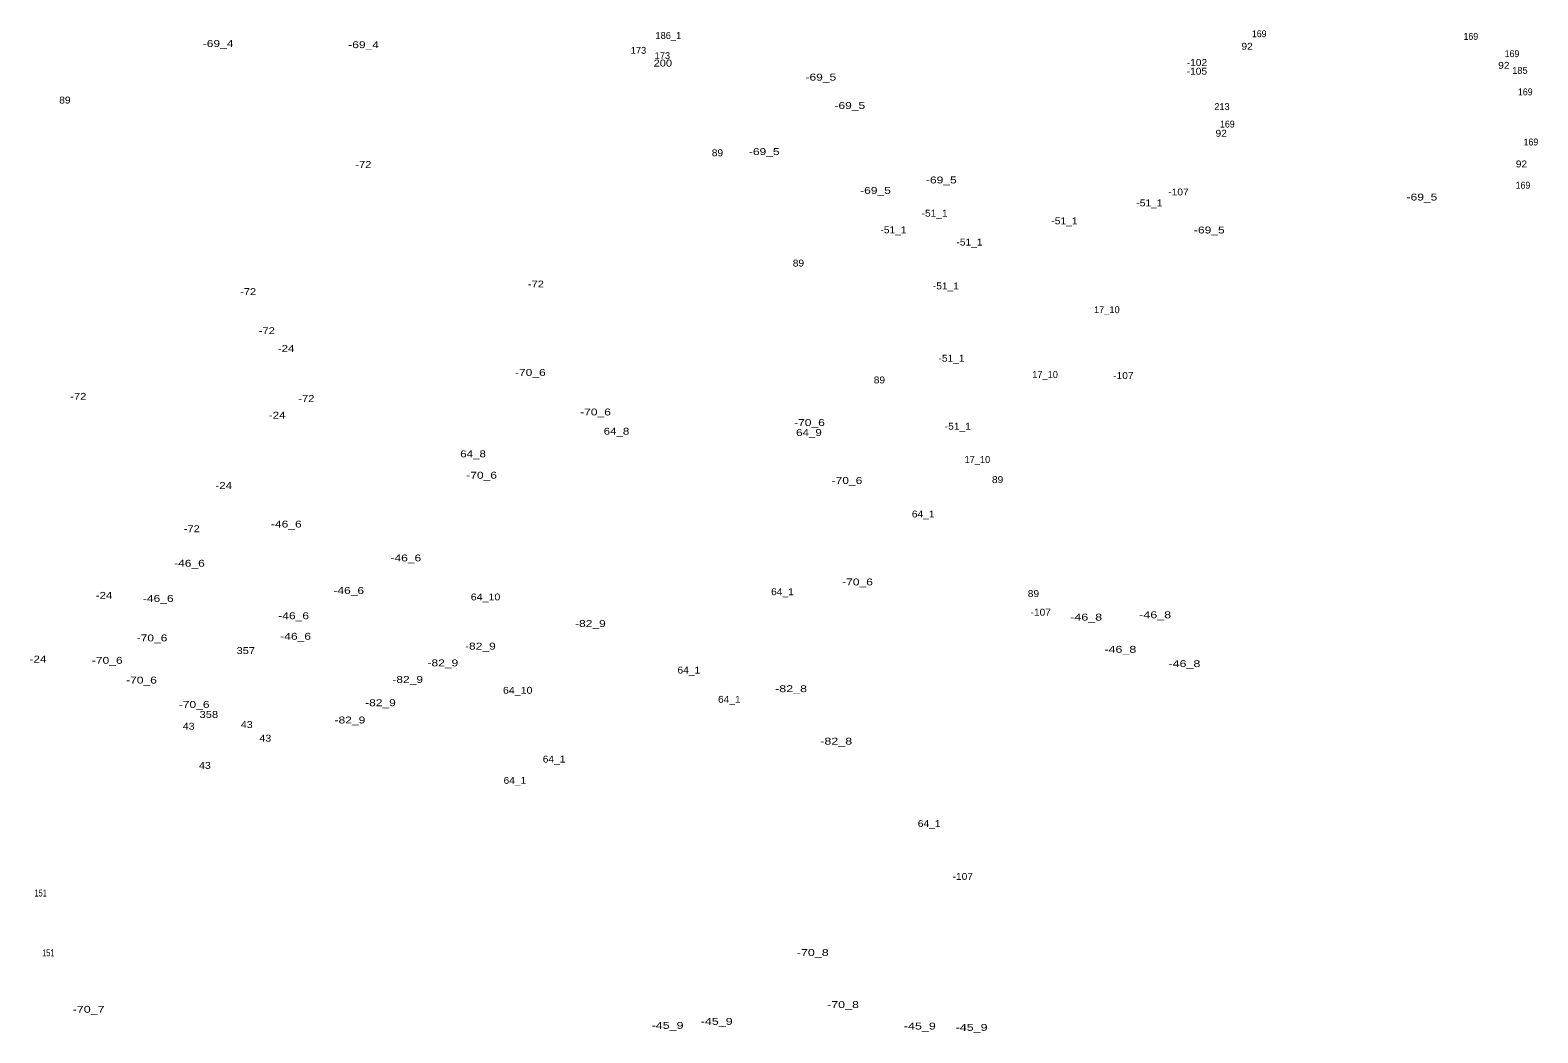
# Model space of a CAD drawing. Extents: x -662996 to -659766, y -998554 to -993949.
# Drawn here: x -660755 to -659883, y -997415 to -996835 of the extents above; entities that cross this region are included whole.
import ezdxf
from ezdxf.enums import TextEntityAlignment as Align

# ---------------------------------------------------------------- set-up
doc = ezdxf.new("R2010")
doc.units = 0
doc.header["$LTSCALE"] = 1.6
doc.layers.add('24', color=7, linetype='Continuous')

msp = doc.modelspace()

# ---------------------------------------------------------------- texts
at = {"layer": '24'}
for s, width, p in [('-69_4', 1.3, (-660646.681, -996844.98)), ('169', 0.95, (-660044.42, -996839.3)), ('169', 0.95, (-659922, -996840.84)), ('-69_4', 1.3, (-660562.52, -996845.64)), ('92', 1.1, (-660051.45, -996846.57)), ('169', 0.95, (-659898.19, -996850.83)), ('200', 1.2, (-660389.419, -996856.3)), ('-105', 1.1, (-660080.5, -996860.99)), ('-102', 1.1, (-660080.451, -996855.92)), ('92', 1.1, (-659902.91, -996857.58)), ('-69_5', 1.3, (-660298.01, -996864.43)), ('89', 1.1, (-660735.31, -996877.66)), ('169', 0.95, (-659890.51, -996872.92)), ('-69_5', 1.3, (-660281.26, -996880.81)), ('92', 1.1, (-660066.42, -996896.89)), ('169', 0.95, (-660062.85, -996891.55)), ('169', 0.95, (-659887.24, -996901.92)), ('-72', 1.2, (-660562.671, -996914.92)), ('89', 1.1, (-660357.83, -996908.16)), ('-69_5', 1.3, (-660330.76, -996907.48)), ('92', 1.1, (-659892.74, -996914.62)), ('-69_5', 1.3, (-660228.32, -996923.87)), ('-69_5', 1.3, (-660266.4, -996929.95)), ('-107', 1.1, (-660091.13, -996930.82)), ('169', 0.95, (-659891.85, -996926.89)), ('-51_1', 1.1, (-660107.97, -996937.14)), ('-69_5', 1.3, (-659950.29, -996933.76)), ('-51_1', 1.1, (-660232.199, -996943.1)), ('-51_1', 1.1, (-660157.13, -996947.52)), ('-51_1', 1.1, (-660256.01, -996952.7)), ('-69_5', 1.3, (-660073.3, -996952.81)), ('-51_1', 1.1, (-660212.04, -996959.8)), ('89', 1.1, (-660310.98, -996971.93)), ('-72', 1.2, (-660462.851, -996984.06)), ('-72', 1.2, (-660629.311, -996988.44)), ('-51_1', 1.1, (-660225.669, -996985.16)), ('-72', 1.2, (-660618.49, -997011.02)), ('-24', 1.25, (-660607.34, -997021.34)), ('-51_1', 1.1, (-660222.4, -997026.98)), ('-70_6', 1.3, (-660466.06, -997035.2)), ('-107', 1.1, (-660123.01, -997036.97)), ('89', 1.1, (-660264.13, -997039.54)), ('-72', 1.2, (-660727.561, -997049.02)), ('-72', 1.2, (-660595.64, -997050.26)), ('-24', 1.25, (-660612.52, -997059.95)), ('-70_6', 1.3, (-660428.36, -997058.06)), ('64_8', 1.25, (-660416.25, -997069.2)), ('-70_6', 1.3, (-660304.6, -997064.16)), ('64_9', 1.25, (-660304.9, -997069.95)), ('-51_1', 1.1, (-660218.77, -997066.3)), ('64_8', 1.25, (-660499.199, -997082.27)), ('-70_6', 1.3, (-660494.25, -997094.63)), ('-70_6', 1.3, (-660282.89, -997097.68)), ('89', 1.1, (-660195.77, -997097.17)), ('-24', 1.25, (-660643.43, -997100.58)), ('-46_6', 1.3, (-660607.221, -997122.87)), ('64_1', 1.1, (-660238.819, -997117.05)), ('-72', 1.2, (-660661.91, -997125.59)), ('-46_6', 1.3, (-660663.28, -997145.54)), ('-46_6', 1.3, (-660538.091, -997142.46)), ('-70_6', 1.3, (-660276.8, -997156.35)), ('-24', 1.25, (-660712.67, -997164.11)), ('-46_6', 1.3, (-660681.331, -997165.9)), ('-46_6', 1.3, (-660571.12, -997161.29)), ('64_10', 1.15, (-660491.99, -997165.03)), ('64_1', 1.1, (-660320.24, -997162)), ('89', 1.1, (-660175.03, -997163.07)), ('-46_6', 1.3, (-660602.99, -997175.89)), ('-107', 1.1, (-660170.81, -997173.83)), ('-46_8', 1.35, (-660144.54, -997176.7)), ('-46_8', 1.35, (-660104.6, -997175.35)), ('-82_9', 1.3, (-660431.32, -997180.4)), ('-70_6', 1.3, (-660684.92, -997188.73)), ('-46_6', 1.3, (-660601.841, -997187.79)), ('-82_9', 1.3, (-660494.96, -997193.49)), ('-24', 1.25, (-660750.88, -997200.99)), ('-70_6', 1.3, (-660710.82, -997201.68)), ('357', 1.2, (-660630.67, -997196.05)), ('-82_9', 1.3, (-660516.67, -997203.15)), ('-46_8', 1.35, (-660124.76, -997195.33)), ('64_1', 1.1, (-660374.38, -997207.33)), ('-46_8', 1.35, (-660087.7, -997203.59)), ('-70_6', 1.3, (-660691.01, -997213.11)), ('-82_9', 1.3, (-660537.02, -997212.75)), ('64_10', 1.15, (-660473.37, -997219.01)), ('-82_8', 1.35, (-660315.24, -997218.08)), ('-70_6', 1.3, (-660660.55, -997227.2)), ('-82_9', 1.3, (-660552.76, -997226.2)), ('64_1', 1.1, (-660350.959, -997224.23)), ('358', 1.2, (-660652.049, -997232.97)), ('-82_9', 1.3, (-660570.43, -997236.18)), ('43', 1.15, (-660663.73, -997239.79)), ('43', 1.15, (-660630.13, -997238.83)), ('43', 1.15, (-660619.37, -997246.71)), ('-82_8', 1.35, (-660289.13, -997248.43)), ('43', 1.15, (-660654.319, -997262.46)), ('64_1', 1.1, (-660452.34, -997258.8)), ('64_1', 1.1, (-660474.99, -997271.1)), ('64_1', 1.1, (-660235.37, -997296.07)), ('-107', 1.1, (-660215.9, -997326.64)), ('151', 0.8, (-660749.34, -997336.26)), ('151', 0.8, (-660744.92, -997370.83)), ('-70_8', 1.35, (-660302.71, -997370.68)), ('-70_7', 1.35, (-660721.571, -997403.52)), ('-70_8', 1.35, (-660285.19, -997400.78)), ('-45_9', 1.35, (-660358.26, -997410.49)), ('-45_9', 1.35, (-660386.67, -997412.8)), ('-45_9', 1.35, (-660240.75, -997413.18)), ('-45_9', 1.35, (-660210.8, -997413.95))]:
    msp.add_text(s, height=4, dxfattribs=dict(at, width=width)).set_placement(p, align=Align.CENTER)
for s, p in [('186_1', (-660386.25, -996840.31)), ('173', (-660403.5, -996848.91)), ('173', (-660389.671, -996851.98)), ('185', (-659893.61, -996860.51)), ('213', (-660065.959, -996881.46)), ('17_10', (-660132.59, -996998.9)), ('17_10', (-660168.3, -997036.36)), ('17_10', (-660207.47, -997085.53))]:
    msp.add_text(s, height=4, dxfattribs=at).set_placement(p, align=Align.CENTER)

doc.saveas('drawing.dxf')
